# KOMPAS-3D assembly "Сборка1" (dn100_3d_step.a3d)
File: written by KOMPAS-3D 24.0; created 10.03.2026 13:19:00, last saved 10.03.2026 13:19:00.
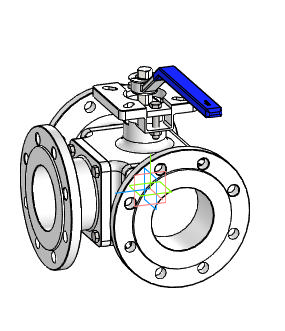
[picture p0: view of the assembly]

Document properties: Автор: R2D2; Полное имя файла: E:\Работа\Зайцев\BV3232P(4pc)-FP-3WL-F-ISO-H Кран шаровой DN.ru Ду15-100 Ру16\DN100\исходные материалы\dn100_3d_step.a3d

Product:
- Component [detail]: Деталь  | qty 1  | Автор: R2D2; source file: Деталь Деталь.m3d
- Component [detail]: Деталь1  | qty 1  | Автор: R2D2; source file: Деталь1 Деталь1.m3d
- Component [detail]: AS 1110 - M10 x 50  | qty 1  | Автор: R2D2; source file: AS 1110 - M10 x 50 AS 1110 - M10 x 50.m3d
- Component [detail]: AS 1110 - M10 x 50  | qty 1  | Комментарий: Болты и винты   шестигранные точные   метрические ISO; Автор: R2D2; additional columns: Сталь, мягкая; source file: AS 1110 - M10 x 50 AS 1110 - M10 x 50.m3d
- Component [detail]: ANSI B18.2.4.2M - M10x1,5 - 16  | designation ANSI B18.2.4.2M - M10x1,5  | qty 1  | Автор: R2D2; source file: ANSI B18.2.4.2M - M10x1,5 ANSI B18.2.4.2M - M10x1,5 - 16.m3d
- Component [detail]: ANSI B18.2.4.2M - M10x1,5 - 16  | designation ANSI B18.2.4.2M - M10x1,5  | qty 1  | Комментарий: Типы метрических   шестигранных гаек   2; Автор: R2D2; additional columns: Сталь, мягкая; source file: ANSI B18.2.4.2M - M10x1,5 ANSI B18.2.4.2M - M10x1,5 - 16.m3d
- Component [detail]: AS 1110 - M10 x 16  | qty 1  | Автор: R2D2; source file: AS 1110 - M10 x 16 AS 1110 - M10 x 16.m3d
- Component [detail]: AS 1110 - M10 x 16  | qty 11  | Комментарий: Болты и винты   шестигранные точные   метрические ISO; Автор: R2D2; additional columns: Сталь, мягкая; source file: AS 1110 - M10 x 16 AS 1110 - M10 x 16.m3d
- Part/product: Сборка1

Referenced files in E:\Работа\Зайцев\BV3232P(4pc)-FP-3WL-F-ISO-H Кран шаровой DN.ru Ду15-100 Ру16\DN100\исходные материалы\: Деталь Деталь.m3d, Деталь1 Деталь1.m3d, AS 1110 - M10 x 50 AS 1110 - M10 x 50.m3d, ANSI B18.2.4.2M - M10x1,5 ANSI B18.2.4.2M - M10x1,5 - 16.m3d, AS 1110 - M10 x 16 AS 1110 - M10 x 16.m3d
